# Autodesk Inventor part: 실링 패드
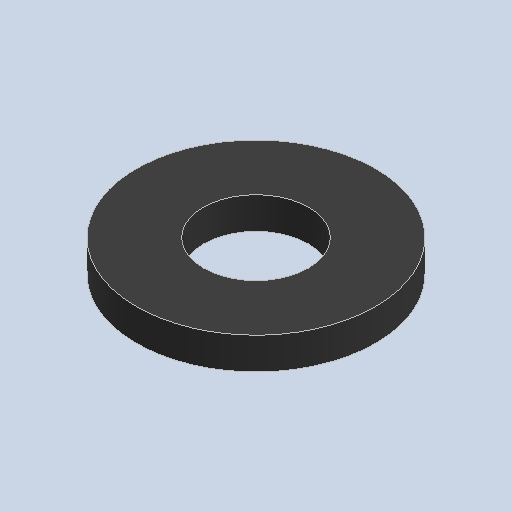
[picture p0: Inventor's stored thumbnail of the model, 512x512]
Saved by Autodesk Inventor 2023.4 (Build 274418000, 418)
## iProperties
Created: 2024-09
Part Number: 실링 패드
Material: 고무
Document SubType Name: Modeling
Designer: 11
Density: 0.93 g/cm^3
Appearance: 기본값
Author: jhkim
Sending System: Autodesk Inventor 2025
Preprocessor: ST-DEVELOPER v20
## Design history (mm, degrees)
node "실링 패드1"
node "솔리드2"
node "솔리드1"
